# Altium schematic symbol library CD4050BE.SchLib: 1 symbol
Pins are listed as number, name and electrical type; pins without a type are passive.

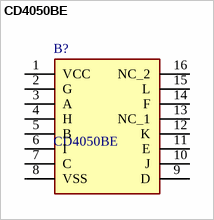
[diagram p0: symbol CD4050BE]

## CD4050BE
designator B?
CD4050BE, Hex Inverter Buffer, Converter, 26mA -0.5  20 V 16-Pin PDIP; Manufacturer_Name: Texas Instruments; Geometry.Height: 5.08mm
footprint DIP794W53P254L1930H508Q16N
pins: 1 VCC, 2 G, 3 A, 4 H, 5 B, 6 I, 7 C, 8 VSS, 9 D, 10 J, 11 E, 12 K, 13 NC_1, 14 F, 15 L, 16 NC_2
